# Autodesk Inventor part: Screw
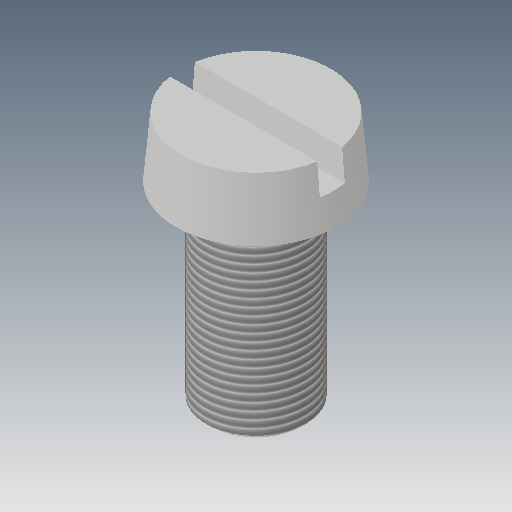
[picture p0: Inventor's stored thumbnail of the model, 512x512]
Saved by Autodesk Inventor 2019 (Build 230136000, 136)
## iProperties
Created: 2016-05
Part Number: Screw
Material: Generic
Document SubType Name: Modeling
Designer: CADCIM
Density: 1 g/cm^3
Appearance: Default
Author: CADCIM
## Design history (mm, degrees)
sketch "Sketch1"
  geometry: C1 r 16 at (0, 0); 1 further point
  constraints: 1 centre point, 1 coincident
  dimensions: "d0" = 32 diameter of C1
extrude "Extrusion1" new body sketch "Sketch1" distance "d1" = 12; taper "d2" = -5 deg
sketch "Sketch2"
  geometry: C1 r 10 at (0, 0); 1 further point
  constraints: 1 centre point, 1 coincident
  dimensions: "d4" = 20 diameter of C1
extrude "Extrusion2" join sketch "Sketch2" distance "d5" = 38; taper "d6" = 0 deg
workplane "Work Plane1"
thread "Thread1" dims "d10" = 10, "d11" = 0
chamfer "Chamfer1" distance "d12" = 0.9; stored, may be unused: second distance "d13" = 2, angle "d14" = 45 deg
sketch "Sketch4"
  geometry: L1 (-19.014, -2.5)-(20.179, -2.5); L2 (20.179, -2.5)-(20.179, 2.5); L3 (20.179, 2.5)-(-19.014, 2.5); L4 (-19.014, 2.5)-(-19.014, -2.5); L5 (0, 0)-(-19.039, 0)
  constraints: 10 end point, 2 horizontal, 2 parallel, 1 perpendicular, 1 other
  dimensions: "d15" = 5 distance of L3.end L1.start
extrude "Extrusion4" cut sketch "Sketch4" distance "d16" = 6; taper "d17" = 0 deg
body "Solid1"
